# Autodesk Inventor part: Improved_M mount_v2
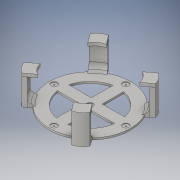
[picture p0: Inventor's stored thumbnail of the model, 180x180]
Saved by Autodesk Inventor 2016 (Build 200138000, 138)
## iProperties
Created: 2020-11
Part Number: Improved_M mount_v2
Material: Generic
Document SubType Name: Modeling
Designer: Rowan
Density: 1 g/cm^3
Appearance: Default
Part Number: Improved_M mount_v2_3DPrint
Author: Rowan
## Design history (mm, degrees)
sketch "Sketch1" dims "d37" = 93.98 (computed from d0)
  geometry: L1 (8.748, 46.168)-(8.748, 6.434); L2 (8.748, -11.066)-(8.748, -46.168); L3 (-8.752, -46.168)-(-8.752, -11.066); L4 (-46.547, 6.434)-(-9.631, 6.434); L5 (8.748, 6.434)-(46.547, 6.434); L6 (45.668, -11.066)-(8.748, -11.066); L7 (-8.752, -11.066)-(-45.668, -11.066); L8 (8.748, -9.308)-(8.75, -9.31); L9 (-9.631, 6.434)-(-9.631, 45.992); C1 r 66.04 at (0, 0); C2 r 1 at (0, -58.513); C3 r 1 at (58.563, 0); C4 r 1 at (0, 58.563); C5 r 1 at (-58.563, 0); C6 r 1 at (0, 0); 3 further points
  constraints: 18 end point, 7 parallel, 6 centre point, 4 coincident, 2 collinear, 2 horizontal, 2 vertical, 15 other
  dimensions: "d0" = 132.08 diameter of C1; "d11" = 17.50035 distance between parallel lines of L6 L5; "d12" = 17.50035 distance between parallel lines of L4 L7 (= d11); "d16" = 17.50035 distance between parallel lines of L2 L3 (= d11); "d20" = 2 diameter of C2; "d25" = 360 deg dimension on point (0, 0) C2.centre (derived); "d27" = 2 diameter of C6; "d35" = 11.06594 distance from line of C1.centre L6; "d36" = 8.74835 distance from line of point (0, 0) L2
extrude "Extrusion1" new body sketch "Sketch1" distance "d28" = 3; taper "d29" = 0 deg
sketch "Sketch2"
  geometry: C1 r 5 at (0, 0); C2 r 1 at (-58.563, 0) reference; C3 r 5 at (-58.563, 0); C4 r 1 at (0, 58.513) reference; C5 r 5.004 at (0, 58.513); C6 r 5 at (58.563, 0); C7 r 1 at (58.563, 0) reference; C8 r 1 at (0, -58.563) reference; C9 r 5.004 at (0, -58.563); 1 further point
  constraints: 5 centre point, 5 coincident
  dimensions: "d30" = 10 diameter of C1; "d31" = 10 diameter of C3; "d38" = 10.0076 diameter of C5; "d39" = 10 diameter of C6; "d40" = 10.0076 diameter of C9
extrude "Extrusion2" cut sketch "Sketch2" distance "d41" = 1; taper "d42" = 0 deg
sketch "Sketch3"
  geometry: L1 (8.748, -11.066)-(45.668, -11.066) reference; L2 (-68.433, -38.46)-(-56.757, -28.477); L3 (-55.613, -55.403)-(-42.832, -46.88); L4 (38.46, -68.433)-(28.477, -56.757); L5 (55.403, -55.613)-(46.88, -42.832); L6 (68.433, 38.46)-(56.757, 28.477); L7 (55.613, 55.403)-(42.832, 46.88); L8 (-38.46, 68.433)-(-28.477, 56.757); L9 (-55.403, 55.613)-(-46.88, 42.832); L10 (-62.599, -47.367)-(-52.663, -39.849); C1 r 1 at (0, 0) reference; C2 r 1 at (0, 0) reference; A1 r 78.5 centre (0, 0) between (-68.433, -38.46) and (-55.613, -55.403); A2 r 63.5 centre (0, 0) between (-56.757, -28.477) and (-42.832, -46.88); A3 r 63.5 centre (0, 0) between (28.477, -56.757) and (46.88, -42.832); A4 r 78.5 centre (0, 0) between (38.46, -68.433) and (55.403, -55.613); A5 r 63.5 centre (0, 0) between (56.757, 28.477) and (42.832, 46.88); A6 r 78.5 centre (0, 0) between (68.433, 38.46) and (55.613, 55.403); A7 r 63.5 centre (0, 0) between (-28.477, 56.757) and (-46.88, 42.832); A8 r 78.5 centre (0, 0) between (-38.46, 68.433) and (-55.403, 55.613); 6 further points
  constraints: 21 point on circle, 18 end point, 8 centre point, 2 coincident, 1 line through centre, 46 other
  dimensions: "d48" = 21.24637 distance of L2.start L3.start; "d49" = 78.5 radius of A1; "d53" = 360 deg dimension on point (0, 0) L2.start (derived); "d96" = 15.24 distance from line of point (0, 0) L2; "d97" = 63.5 radius of A3
extrude "Extrusion3" join sketch "Sketch3" distance "d55" = 5; taper "d56" = 0 deg
sketch "Sketch4"
  geometry: L1 (-58.743, -30.175)-(-68.433, -38.46) reference; L2 (-62.599, -47.367)-(-32.752, -24.783); L3 (-50.265, -51.889)-(-55.613, -55.403); L4 (-68.433, -38.46)-(-63.598, -34.268); L5 (-55.613, -55.403)-(-45.006, -48.329) reference; L6 (51.889, -50.265)-(55.403, -55.613); L7 (38.46, -68.433)-(34.268, -63.598); L8 (50.265, 51.889)-(55.613, 55.403); L9 (68.433, 38.46)-(63.598, 34.268); L10 (-51.889, 50.265)-(-55.403, 55.613); L11 (-38.46, 68.433)-(-34.268, 63.598); A1 r 78.5 centre (0, 0) between (-68.433, -38.46) and (-55.613, -55.403) reference; A2 r 46.99 centre (0, 0) between (-46.547, -6.434) and (-8.748, -46.168) reference; A3 r 26.916 centre (-42.302, -32.009) between (-68.433, -38.46) and (-55.613, -55.403); A4 r 52.956 centre (-15.632, -11.828) between (-63.598, -34.268) and (-50.265, -51.889); A5 r 52.956 centre (11.828, -15.632) between (34.268, -63.598) and (51.889, -50.265); A6 r 26.916 centre (32.009, -42.302) between (38.46, -68.433) and (55.403, -55.613); A7 r 52.956 centre (15.632, 11.828) between (63.598, 34.268) and (50.265, 51.889); A8 r 26.916 centre (42.302, 32.009) between (68.433, 38.46) and (55.613, 55.403); A9 r 52.956 centre (-11.828, 15.632) between (-34.268, 63.598) and (-51.889, 50.265); A10 r 26.916 centre (-32.009, 42.302) between (-38.46, 68.433) and (-55.403, 55.613)
  constraints: 18 end point, 17 point on circle, 8 centre point, 2 line through centre, 1 equal length, 42 other
  dimensions: "d98" = 5.34801 horizontal distance of L3.start L3.end; "d99" = 15.7659 distance from line of A1.centre L3; "d100" = 26.91584 radius of A3; "d101" = 52.95592 radius of A4; "d104" = 360 deg dimension on A1.centre A4.centre (derived)
extrude "Extrusion4" join sketch "Sketch4" distance "d63" = 40; taper "d65" = 0 deg; dims "d64" = 3, "d66" = 0
sketch "Sketch5"
  geometry: L1 (-55.613, -55.403)-(-40.919, -44.498); L2 (-53.945, -27.283)-(-68.433, -38.46); L3 (-63.766, -48.25)-(0, 0); L4 (55.403, -55.613)-(44.498, -40.919); L5 (27.283, -53.945)-(38.46, -68.433); L6 (55.613, 55.403)-(40.919, 44.498); L7 (53.945, 27.283)-(68.433, 38.46); L8 (-55.403, 55.613)-(-44.498, 40.919); L9 (-27.283, 53.945)-(-38.46, 68.433); C1 r 1 at (0, 0) reference; C2 r 1 at (0, 0) reference; A1 r 26.916 centre (-42.302, -32.009) between (-68.433, -38.46) and (-55.613, -55.403) reference; A2 r 26.916 centre (-42.302, -32.009) between (-68.433, -38.46) and (-55.613, -55.403); A3 r 26.029 centre (-28.544, -21.598) between (-53.945, -27.283) and (-40.919, -44.498); A4 r 26.916 centre (32.009, -42.302) between (38.46, -68.433) and (55.403, -55.613); A5 r 26.029 centre (21.598, -28.544) between (27.283, -53.945) and (44.498, -40.919); A6 r 26.916 centre (42.302, 32.009) between (68.433, 38.46) and (55.613, 55.403); A7 r 26.029 centre (28.544, 21.598) between (53.945, 27.283) and (40.919, 44.498); A8 r 26.916 centre (-32.009, 42.302) between (-38.46, 68.433) and (-55.403, 55.613); A9 r 26.029 centre (-21.598, 28.544) between (-27.283, 53.945) and (-44.498, 40.919); 3 further points
  constraints: 18 end point, 17 point on circle, 8 centre point, 1 equal length, 46 other
  dimensions: "d110" = 360 deg dimension on C1.centre L1.start (derived)
extrude "Extrusion5" join sketch "Sketch5" distance "d89" = 5; taper "d90" = 0 deg
fillet "Fillet6" dims "d113" = 7.62
fillet "Fillet7" dims "d114" = 12.7
fillet "Fillet8" dims "d115" = 7.62
fillet "Fillet9" dims "d116" = 7.62
fillet "Fillet10" dims "d117" = 7.62
fillet "Fillet11" dims "d118" = 12.7
fillet "Fillet12" dims "d119" = 12.7
fillet "Fillet13" dims "d120" = 12.7
body "Solid1"
other parameters: "d1" = 115, "d3" = 17.5006
